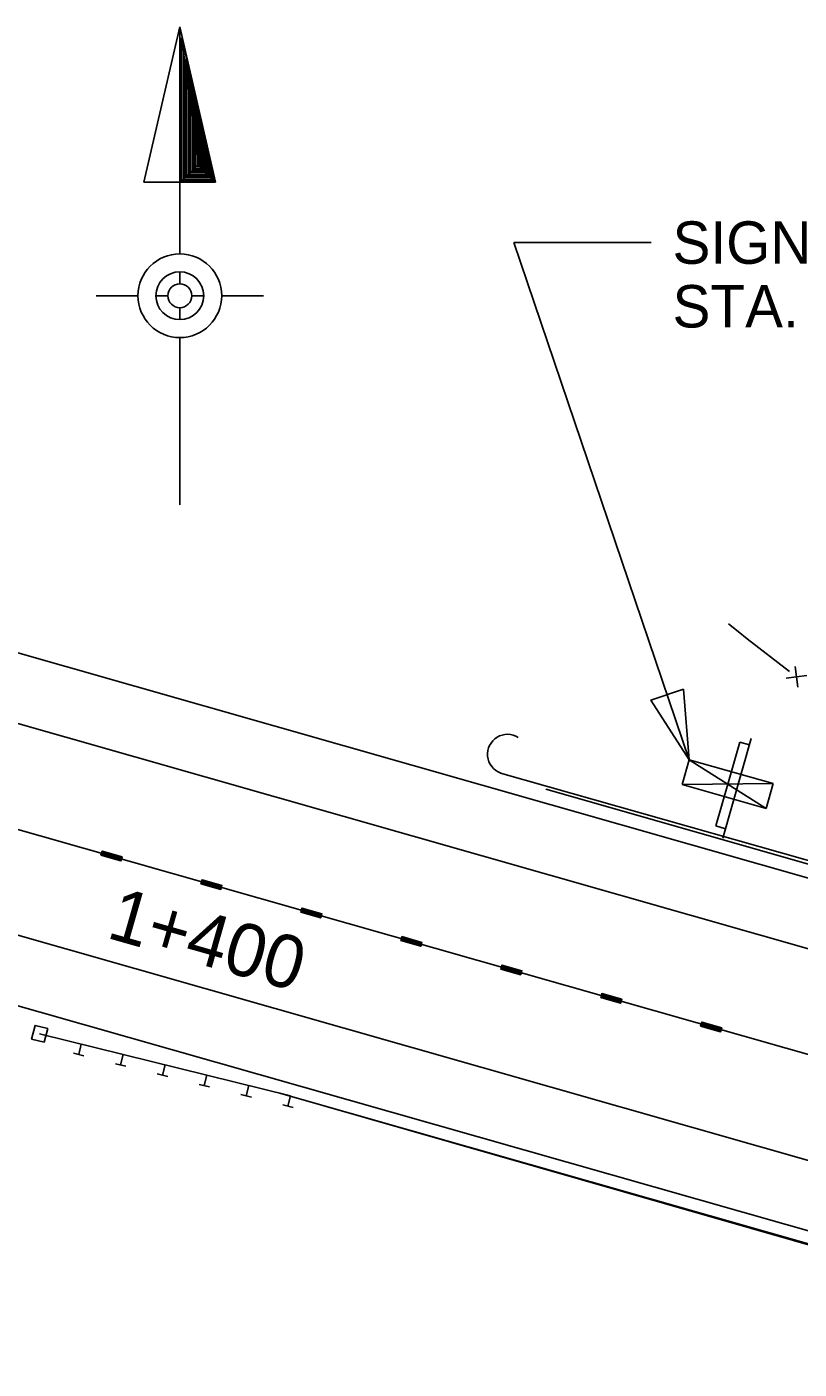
# Model space of a CAD drawing. Extents: x 3829340 to 3831660, y 499389 to 501171.
# Drawn here: x 3829843.8 to 3829898.3, y 499450.7 to 499545.6 of the extents above; entities that cross this region are included whole.
import ezdxf

# ---------------------------------------------------------------- set-up
doc = ezdxf.new("R2010")
doc.units = 0
for name, color, linetype in [('DIM TXT', 7, 'Continuous'), ('Level 15', 7, 'Continuous'), ('Level 21', 7, 'Continuous'), ('Level 26', 7, 'Continuous'), ('Level 27', 7, 'Continuous'), ('Level 43', 7, 'Continuous'), ('Level 48', 7, 'Continuous'), ('Level 53', 7, 'Continuous')]:
    doc.layers.add(name, color=color, linetype=linetype)

msp = doc.modelspace()

# ---------------------------------------------------------------- linework, layer by layer
at = {"layer": 'DIM TXT'}
for p in [(3829890.578, 499493.762), (3829887.896, 499530.313)]:
    msp.add_line(p, (3829878.176, 499530.313), dxfattribs=at)
msp.add_lwpolyline([(3829890.167, 499498.755), (3829890.578, 499493.762), (3829887.866, 499497.974)], close=True, dxfattribs=at)
at = {"layer": 'Level 21'}
for p, q in [((3829898.05, 499500.354), (3829898.236, 499498.895)), ((3829897.413, 499499.535), (3829898.872, 499499.717))]:
    msp.add_line(p, q, dxfattribs=at)
for points in [[(3829893.346, 499503.361), (3829894.031, 499502.821)], [(3829894.029, 499502.821), (3829894.679, 499502.303), (3829897.667, 499499.992)]]:
    msp.add_lwpolyline(points, dxfattribs=at)
at = {"layer": 'Level 26'}
for p, q in [((3829836.105, 499503.308), (3829917.328, 499480.163)), ((3829835.509, 499498.489), (3829952.572, 499465.133)), ((3829833.722, 499484.034), (3829950.778, 499450.681)), ((3829833.126, 499479.216), (3829931.848, 499451.085))]:
    msp.add_line(p, q, dxfattribs=at)
at = {"layer": 'Level 27'}
for p, q in [((3829907.932, 499484.076), (3829877.253, 499492.818)), ((3829911.208, 499482.904), (3829880.444, 499491.67)), ((3829862.414, 499470), (3829844.674, 499474.385)), ((3829847.447, 499472.913), (3829847.629, 499473.653)), ((3829847.817, 499472.823), (3829847.077, 499473.006)), ((3829850.405, 499472.184), (3829850.587, 499472.923)), ((3829850.775, 499472.091), (3829850.035, 499472.274)), ((3829853.73, 499471.362), (3829852.991, 499471.544)), ((3829853.361, 499471.452), (3829853.543, 499472.191)), ((3829856.319, 499470.722), (3829856.501, 499471.462)), ((3829856.688, 499470.63), (3829855.949, 499470.812)), ((3829859.277, 499469.99), (3829859.459, 499470.73)), ((3829859.644, 499469.9), (3829858.907, 499470.083)), ((3829862.227, 499469.261), (3829862.409, 499470)), ((3829920.482, 499453.414), (3829862.387, 499469.967)), ((3829862.597, 499469.171), (3829861.857, 499469.353))]:
    msp.add_line(p, q, dxfattribs=at)
msp.add_lwpolyline([(3829845.016, 499473.783), (3829845.26, 499474.754), (3829844.36, 499474.974), (3829844.119, 499474.006)], close=True, dxfattribs=at)
msp.add_lwpolyline([(3829861.654, 499470.195), (3829913.134, 499455.409), (3829923.436, 499453.274)], dxfattribs=at)
msp.add_ellipse((3829877.736, 499494.144), major_axis=(0.807, 1.157), ratio=0.999995, start_param=0.035909, end_param=3.402363, dxfattribs=at)
at = {"layer": 'Level 43'}
for p, q in [((3829892.952, 499488.213), (3829894.957, 499495.253)), ((3829893.298, 499492.042), (3829894.142, 499495.004)), ((3829894.144, 499495.005), (3829894.83, 499494.809)), ((3829890.079, 499492.008), (3829890.58, 499493.761)), ((3829890.578, 499493.762), (3829896.514, 499492.071)), ((3829890.578, 499493.762), (3829896.015, 499490.317)), ((3829896.514, 499492.071), (3829890.081, 499492.008)), ((3829890.081, 499492.008), (3829896.015, 499490.317)), ((3829892.454, 499489.079), (3829893.298, 499492.042)), ((3829896.016, 499490.316), (3829896.513, 499492.069)), ((3829892.456, 499489.079), (3829893.143, 499488.883))]:
    msp.add_line(p, q, dxfattribs=at)
at = {"layer": 'Level 48'}
msp.add_line((3829834.616, 499491.262), (3829950.898, 499458.128), dxfattribs=at)
for points in [[(3829849.013, 499487.006), (3829850.424, 499486.603), (3829850.505, 499486.884), (3829849.094, 499487.29)], [(3829849.053, 499487.029), (3829850.404, 499486.644), (3829850.468, 499486.867), (3829849.114, 499487.25)], [(3829849.094, 499487.05), (3829850.38, 499486.684), (3829850.428, 499486.843), (3829849.138, 499487.209)], [(3829849.125, 499487.067), (3829850.363, 499486.722), (3829850.39, 499486.823), (3829849.155, 499487.175)], [(3829849.152, 499487.087), (3829850.35, 499486.745), (3829850.367, 499486.809), (3829849.172, 499487.148)], [(3829849.179, 499487.097), (3829850.333, 499486.769), (3829850.34, 499486.793), (3829849.185, 499487.124)], [(3829856.076, 499484.995), (3829857.488, 499484.593), (3829857.565, 499484.874), (3829856.157, 499485.28)], [(3829856.113, 499485.016), (3829857.464, 499484.63), (3829857.525, 499484.853), (3829856.178, 499485.239)], [(3829856.154, 499485.039), (3829857.444, 499484.67), (3829857.488, 499484.83), (3829856.198, 499485.198)], [(3829856.188, 499485.056), (3829857.423, 499484.704), (3829857.457, 499484.813), (3829856.218, 499485.164)], [(3829856.218, 499485.073), (3829857.406, 499484.731), (3829857.427, 499484.799), (3829856.235, 499485.138)], [(3829856.242, 499485.087), (3829857.396, 499484.759), (3829857.403, 499484.782), (3829856.246, 499485.114)], [(3829863.136, 499482.985), (3829864.547, 499482.582), (3829864.628, 499482.863), (3829863.217, 499483.266)], [(3829863.173, 499483.005), (3829864.524, 499482.62), (3829864.591, 499482.843), (3829863.238, 499483.229)], [(3829863.214, 499483.026), (3829864.503, 499482.66), (3829864.551, 499482.819), (3829863.261, 499483.188)], [(3829863.248, 499483.046), (3829864.486, 499482.694), (3829864.513, 499482.799), (3829863.278, 499483.151)], [(3829863.275, 499483.063), (3829864.47, 499482.721), (3829864.49, 499482.782), (3829863.292, 499483.124)], [(3829863.302, 499483.073), (3829864.456, 499482.748), (3829864.463, 499482.768), (3829863.309, 499483.097)], [(3829870.196, 499480.971), (3829871.611, 499480.569), (3829871.692, 499480.85), (3829870.277, 499481.252)], [(3829870.237, 499480.995), (3829871.59, 499480.609), (3829871.651, 499480.829), (3829870.297, 499481.215)], [(3829870.277, 499481.015), (3829871.567, 499480.65), (3829871.611, 499480.809), (3829870.321, 499481.174)], [(3829870.311, 499481.032), (3829871.546, 499480.68), (3829871.577, 499480.789), (3829870.341, 499481.141)], [(3829870.338, 499481.049), (3829871.529, 499480.707), (3829871.55, 499480.772), (3829870.358, 499481.113)], [(3829870.362, 499481.063), (3829871.516, 499480.731), (3829871.523, 499480.758), (3829870.369, 499481.087)], [(3829877.259, 499478.958), (3829878.67, 499478.558), (3829878.752, 499478.839), (3829877.34, 499479.242)], [(3829877.296, 499478.978), (3829878.647, 499478.596), (3829878.711, 499478.816), (3829877.357, 499479.201)], [(3829877.337, 499479.002), (3829878.623, 499478.633), (3829878.67, 499478.792), (3829877.381, 499479.161)], [(3829877.371, 499479.022), (3829878.61, 499478.667), (3829878.637, 499478.778), (3829877.401, 499479.127)], [(3829877.398, 499479.036), (3829878.596, 499478.697), (3829878.613, 499478.761), (3829877.418, 499479.1)], [(3829877.425, 499479.052), (3829878.579, 499478.721), (3829878.586, 499478.748), (3829877.432, 499479.076)], [(3829884.323, 499476.944), (3829885.73, 499476.545), (3829885.811, 499476.826), (3829884.4, 499477.228)], [(3829884.36, 499476.968), (3829885.71, 499476.582), (3829885.771, 499476.805), (3829884.424, 499477.191)], [(3829884.4, 499476.991), (3829885.69, 499476.622), (3829885.734, 499476.782), (3829884.444, 499477.15)], [(3829884.431, 499477.012), (3829885.669, 499476.656), (3829885.7, 499476.761), (3829884.465, 499477.117)], [(3829884.461, 499477.025), (3829885.652, 499476.687), (3829885.669, 499476.748), (3829884.481, 499477.086)], [(3829884.485, 499477.039), (3829885.639, 499476.71), (3829885.646, 499476.734), (3829884.492, 499477.062)], [(3829891.379, 499474.934), (3829892.794, 499474.531), (3829892.875, 499474.815), (3829891.464, 499475.214)], [(3829891.419, 499474.957), (3829892.77, 499474.572), (3829892.834, 499474.791), (3829891.481, 499475.177)], [(3829891.46, 499474.978), (3829892.75, 499474.612), (3829892.794, 499474.768), (3829891.504, 499475.137)], [(3829891.494, 499474.994), (3829892.729, 499474.646), (3829892.76, 499474.751), (3829891.524, 499475.106)], [(3829891.521, 499475.012), (3829892.716, 499474.67), (3829892.736, 499474.737), (3829891.538, 499475.076)], [(3829891.548, 499475.025), (3829892.702, 499474.697), (3829892.709, 499474.72), (3829891.552, 499475.052)]]:
    msp.add_lwpolyline(points, close=True, dxfattribs=at)
at = {"layer": 'Level 53'}
for p, q in [((3829852.051, 499534.581), (3829854.585, 499545.563)), ((3829857.119, 499534.581), (3829854.585, 499545.563)), ((3829854.585, 499529.518), (3829854.585, 499545.563)), ((3829857.119, 499534.581), (3829852.051, 499534.581)), ((3829854.585, 499527.406), (3829854.585, 499528.243)), ((3829851.627, 499526.556), (3829848.671, 499526.556)), ((3829853.764, 499526.556), (3829852.911, 499526.556)), ((3829854.585, 499526.556), (3829854.585, 499526.556)), ((3829856.288, 499526.556), (3829855.408, 499526.556)), ((3829860.498, 499526.556), (3829857.527, 499526.556)), ((3829854.585, 499524.884), (3829854.585, 499525.719)), ((3829854.585, 499511.773), (3829854.585, 499523.591))]:
    msp.add_line(p, q, dxfattribs=at)
msp.add_lwpolyline([(3829854.711, 499544.786), (3829854.711, 499534.649), (3829856.992, 499534.649), (3829854.838, 499544.279), (3829854.838, 499534.775), (3829856.866, 499534.775), (3829854.964, 499543.266), (3829854.964, 499534.902), (3829856.74, 499534.902), (3829855.093, 499542.377), (3829855.093, 499535.028), (3829856.611, 499535.028), (3829855.219, 499541.364), (3829855.219, 499535.154), (3829856.485, 499535.154), (3829855.345, 499540.477), (3829855.345, 499535.283), (3829856.358, 499535.283), (3829855.472, 499539.464), (3829855.472, 499535.409), (3829856.232, 499535.409), (3829855.598, 499538.577), (3829855.598, 499535.536), (3829856.106, 499535.536), (3829855.724, 499537.562), (3829855.724, 499535.662), (3829855.979, 499535.662), (3829855.853, 499536.423), (3829855.853, 499535.788), (3829854.711, 499534.649), (3829854.711, 499544.786), (3829855.853, 499536.423), (3829855.853, 499535.788), (3829856.992, 499534.649)], dxfattribs=at)
for radius in [2.957, 1.689, 0.845]:
    msp.add_circle((3829854.588, 499526.557), radius, dxfattribs=at)

# ---------------------------------------------------------------- texts
at = {"layer": 'DIM TXT'}
for s, height, p in [('SIGN STRUCTURE', 3.00008, (3829889.396, 499528.813)), ('STA. ', 3.0001, (3829889.396, 499524.312))]:
    msp.add_text(s, height=height, dxfattribs=at).set_placement(p)
at = {"layer": 'Level 15'}
msp.add_text('1+400', height=3.7304, rotation=344.09531, dxfattribs=at).set_placement((3829849.312, 499481.201))

doc.saveas('drawing.dxf')
